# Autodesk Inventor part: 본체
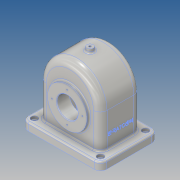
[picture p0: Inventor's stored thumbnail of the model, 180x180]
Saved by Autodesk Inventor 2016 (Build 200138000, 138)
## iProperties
Created: 2016-10
Part Number: 본체
Material: 알루미늄 6061
Document SubType Name: Modeling
Designer: Administrator
Density: 2.7 g/cm^3
Appearance: 알루미늄 - 평지
Mass: 1160.82 g
Surface Area: 1199.98 cm^2
Volume: 429.934 cm^3
Author: Administrator
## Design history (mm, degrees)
sketch "스케치1"
  geometry: L1 (-58, 0)-(58, 0); L2 (58, 0)-(58, -80); L3 (58, -80)-(-58, -80); L4 (-58, -80)-(-58, 0); L5 (-81.2, 0)-(81.2, 0) reference; L6 (0, -107.6)-(0, 85.6) reference; A1 r 58 centre (0, 0) between (58, 0) and (-58, 0); 1 further point
  constraints: 8 end point, 2 parallel, 2 point on circle, 2 point on line, 1 centre point, 1 coincident, 1 collinear, 1 horizontal, 1 perpendicular, 1 other
  dimensions: "d1" = 80 distance of L3.end L1.start; "d2" = 58 radius of A1
extrude "돌출1" new body sketch "스케치1" stored distance "d3" = 77; taper "d4" = 0 deg
fillet "모깎기1" dims "d5" = 13
sketch "스케치3"
  geometry: L1 (0, -25.5)-(0, 25.5) reference; L2 (0, 25.5)-(0, -25.5) reference; L3 (0, -25.5)-(0, -25.5) reference; L4 (0, 25.5)-(0, 25.5) reference; 1 further point
  node "투영된 루프1"
sketch "스케치4"
  geometry: L1 (-30, 16.5)-(120, 16.5); L2 (120, 16.5)-(120, -93.5); L3 (120, -93.5)-(-30, -93.5); L4 (-30, -93.5)-(-30, 16.5); L5 (-30, 16.5)-(120, -93.5); L6 (120, 16.5)-(-30, -93.5); 1 further point
  constraints: 12 end point, 2 midpoint, 2 parallel, 1 horizontal, 1 perpendicular
  dimensions: "d16" = 110 distance of L1.end L2.end; "d17" = 150 distance of L2.end L3.end
extrude "돌출2" join sketch "스케치4" distance "d18" = 15; taper "d19" = 0 deg
fillet "모깎기2" dims "d20" = 12
sketch "스케치6"
  geometry: A1 r 12 centre (-18, -4.5) between (-30, -4.5) and (-18, -16.5) reference; A2 r 12 centre (108, -4.5) between (108, -16.5) and (120, -4.5) reference; A3 r 12 centre (108, 81.5) between (120, 81.5) and (108, 93.5) reference; A4 r 12 centre (-18, 81.5) between (-18, 93.5) and (-30, 81.5) reference; 1 further point
hole "구멍1" sketch "스케치6" at (-18, 81.5), (-18, -4.5), (108, -4.5), (108, 81.5) diameter "d21" = 5; stored, may be unused: countersink angle "d25" = 90 deg, drill point angle "d27" = 118 deg; dims "d22" = 6, "d23" = 12, "d24" = 5, "d26" = 8
fillet "모깎기3" dims "d28" = 3
node "작업 평면1"
sketch "스케치7"
  geometry: C1 r 6 at (0, 0); 1 further point
  constraints: 1 centre point, 1 coincident
  dimensions: "d30" = 12 diameter of C1
extrude "돌출3" join sketch "스케치7" stored distance "d31" = 15; taper "d32" = 0 deg
sketch "스케치9"
  geometry: L1 (-58, -65)-(-58, 0) reference; L2 (58, 0)-(58, -65) reference; L3 (63, -80)-(-63, -80) reference; L4 (-52, -80)-(-52, 0); L5 (52, 0)-(52, -80); L6 (-105, 0)-(105, 0) reference; L7 (0, -108.8)-(0, 92.8) reference; A1 r 58 centre (0, 0) between (58, 0) and (-58, 0) reference; A2 r 52 centre (0, 0) between (52, 0) and (-52, 0); 1 further point
  constraints: 4 end point, 2 point on circle, 2 point on line, 1 centre point
  dimensions: "d45" = 6 radial gap between concentric circles of A1 A2; "d46" = 80 distance of L5.start L5.end; "d47" = 80 distance of L4.start L4.end; "d48" = 104 distance of L5.end L4.start
extrude "돌출4" cut sketch "스케치9" stored distance "d49" = 67; taper "d50" = 0 deg
sketch "스케치10"
  geometry: L1 (-65, 38.5)-(0, 38.5) reference; L2 (-15, 38.5)-(-15, -38.5); L3 (0, -38.5)-(-65, -38.5) reference; L4 (-80, -55)-(-80, -43) reference; L5 (-15, 38.5)-(-15, 43.5); L6 (0, 38.5)-(45, 38.5) reference; L7 (-15, 43.5)-(22.5, 43.5); L8 (22.5, 43.5)-(22.5, 33.5); L9 (52, 33.5)-(0, 33.5) reference; L10 (13, 19.5)-(-15, 19.5); L11 (13, 19.5)-(24.747, 33.5); L12 (24.747, 33.5)-(22.5, 33.5); L13 (58, 25.5)-(0, 25.5) reference; 1 further point
  constraints: 14 end point, 5 point on line, 2 perpendicular, 2 vertical, 1 horizontal, 1 parallel
  dimensions: "d51" = 65 distance between parallel lines of L4 L2; "d52" = 5 distance of L2.start L5.end; "d54" = 37.5 distance of L5.end L7.end; "d114" = 28 distance of L10.end L10.start; "d115" = 50 deg angle of L10 L11; "d116" = 24 distance between parallel lines of L10 L7
revolve "회전1" sketch "스케치10" stored, may be unused: angle "d57" = 90 deg
hole "구멍2" diameter "d60" = 40; stored, may be unused: countersink angle "d64" = 90 deg, drill point angle "d66" = 118 deg; dims "d58" = 10, "d59" = 10, "d61" = 6, "d62" = 12, "d63" = 5, "d65" = 8
sketch "스케치11"
  geometry: C1 r 20 at (0, -15) reference; C2 r 31 at (0, -15)
  constraints: 1 centre point, 1 coincident
  dimensions: "d67" = 62 diameter of C2
extrude "돌출5" join sketch "스케치11" distance "d68" = 10; taper "d69" = 0 deg
sketch "스케치12" dims "d70" = 52
  geometry: L1 (105, 15)-(-105, 15) reference; L2 (0, -93.8)-(0, 107.8) reference; C1 r 31 at (0, 0) reference; 3 further points
  constraints: 1 coincident, 1 point on line, 1 vertical alignment, 2 other
hole "구멍3" sketch "스케치12" at (0, 26) diameter "d71" = 2.459; stored, may be unused: countersink angle "d75" = 90 deg, drill point angle "d77" = 118 deg; dims "d72" = 6, "d73" = 12, "d74" = 5, "d76" = 8
sketch "스케치13" dims "d81" = 58
  geometry: L1 (-105, 15)-(105, 15) reference; L2 (0, -93.8)-(0, 107.8) reference; C1 r 37.5 at (0, 0) reference; 3 further points
  constraints: 1 coincident, 1 point on line, 1 vertical alignment, 2 other
hole "구멍4" sketch "스케치13" at (0, 29) diameter "d82" = 2.459; stored, may be unused: countersink angle "d86" = 90 deg, drill point angle "d88" = 118 deg; dims "d83" = 6, "d84" = 12, "d85" = 5, "d87" = 8
hole "구멍5" diameter "d94" = 4.134; stored, may be unused: countersink angle "d98" = 90 deg, drill point angle "d100" = 118 deg; dims "d92" = 10, "d93" = 10, "d95" = 10, "d96" = 12, "d97" = 5, "d99" = 14.2
node "작업 평면2"
sketch "스케치14" dims "d5" = 13
  geometry: L1 (-108.8, 0)-(92.8, 0) reference; L2 (0, -77)-(0, 77) reference; L3 (0, 38.5)-(-65, 38.5) reference; L4 (-80, 43)-(-80, -43) reference; 2 further points
  constraints: 1 other
  dimensions: "d102" = 38.5 distance from line of point (-40, 0) L3; "d103" = 40 distance from line of L4 point (-40, 0)
feature "엠보싱1" sketch "스케치14" dims "d1" = 80, "d2" = 58, "d81" = 58, "d88" = 118 deg, "d104" = 0.5, "d105" = 0, "d113" = 3
fillet "모깎기5" dims "d106" = 3
chamfer "모따기1" distance "d107" = 1; stored, may be unused: second distance "d108" = 2, angle "d109" = 45 deg
fillet "모깎기6" dims "d110" = 8
feature "면 기울기1" dims angle "d111" = 10 deg
fillet "모깎기7" dims "d112" = 3
fillet "모깎기8" dims "d113" = 3
node "솔리드1"
pattern_circular "원형 패턴1" dims angle "d79" = 360 deg
pattern_circular "원형 패턴2" dims angle "d90" = 360 deg
other parameters: "d29" = 64
